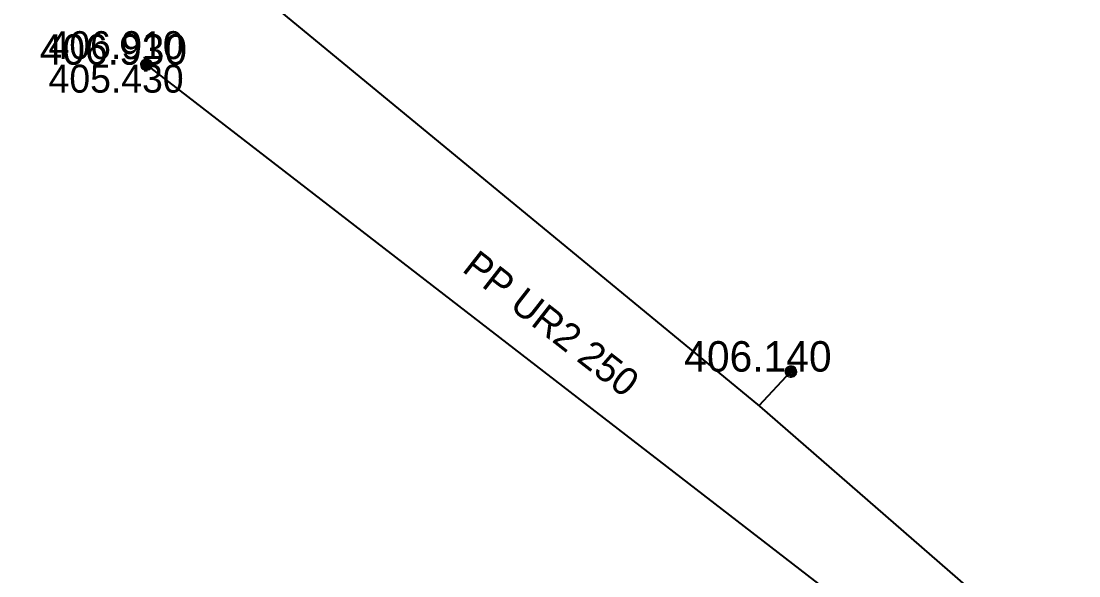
# Model space of a CAD drawing. Extents: x -873619 to -867639, y -1015082 to -1012326.
# Drawn here: x -868171.18 to -868129.55, y -1012747.99 to -1012726.16 of the extents above; entities that cross this region are included whole.
import ezdxf

# ---------------------------------------------------------------- set-up
doc = ezdxf.new("R2010")
doc.units = 0
doc.header["$LTSCALE"] = 0.44
for name, color, linetype, lineweight in [('1', 7, 'Continuous', 13), ('21', 7, 'Continuous', 35), ('32', 7, 'Continuous', 13), ('8', 7, 'Continuous', 13)]:
    doc.layers.add(name, color=color, linetype=linetype, lineweight=lineweight)

msp = doc.modelspace()

# ---------------------------------------------------------------- linework, layer by layer
at = {"layer": '1', "lineweight": 35}
msp.add_line((-868142.136, -1012741.287), (-868140.88, -1012739.954), dxfattribs=at)
msp.add_lwpolyline([(-868094.808, -1012782.506), (-868128.65, -1012753.034), (-868142.107, -1012741.315), (-868163.447, -1012723.713), (-868165.629, -1012721.604), (-868186.647, -1012703.368), (-868189.69, -1012700.802), (-868224.291, -1012669.746), (-868245.779, -1012651.034), (-868246.236, -1012651.387)], dxfattribs=at)
at = {"layer": '1'}
for points in [[(-868166.017, -1012727.87), (-868166.023, -1012727.818), (-868166.04, -1012727.768), (-868166.069, -1012727.724), (-868166.106, -1012727.687), (-868166.151, -1012727.66), (-868166.201, -1012727.643), (-868166.254, -1012727.639), (-868166.306, -1012727.646), (-868166.355, -1012727.665), (-868166.398, -1012727.694), (-868166.434, -1012727.733), (-868166.46, -1012727.778), (-868166.476, -1012727.829), (-868166.479, -1012727.881), (-868166.471, -1012727.933), (-868166.451, -1012727.982), (-868166.42, -1012728.025), (-868166.381, -1012728.059), (-868166.335, -1012728.085), (-868166.284, -1012728.099), (-868166.231, -1012728.101), (-868166.18, -1012728.091), (-868166.132, -1012728.07), (-868166.089, -1012728.039), (-868166.055, -1012727.998), (-868166.031, -1012727.952), (-868166.019, -1012727.901)], [(-868166.047, -1012727.87), (-868166.053, -1012727.821), (-868166.07, -1012727.775), (-868166.098, -1012727.735), (-868166.135, -1012727.703), (-868166.179, -1012727.681), (-868166.227, -1012727.67), (-868166.276, -1012727.67), (-868166.323, -1012727.683), (-868166.366, -1012727.707), (-868166.402, -1012727.74), (-868166.429, -1012727.781), (-868166.445, -1012727.828), (-868166.449, -1012727.877), (-868166.442, -1012727.925), (-868166.423, -1012727.97), (-868166.393, -1012728.01), (-868166.355, -1012728.041), (-868166.311, -1012728.061), (-868166.263, -1012728.071), (-868166.214, -1012728.069), (-868166.167, -1012728.054), (-868166.124, -1012728.029), (-868166.09, -1012727.995), (-868166.064, -1012727.953), (-868166.05, -1012727.906)], [(-868166.077, -1012727.87), (-868166.083, -1012727.825), (-868166.1, -1012727.783), (-868166.128, -1012727.748), (-868166.164, -1012727.721), (-868166.206, -1012727.704), (-868166.251, -1012727.699), (-868166.296, -1012727.705), (-868166.337, -1012727.724), (-868166.372, -1012727.752), (-868166.399, -1012727.789), (-868166.415, -1012727.831), (-868166.419, -1012727.876), (-868166.412, -1012727.921), (-868166.393, -1012727.962), (-868166.364, -1012727.996), (-868166.327, -1012728.022), (-868166.284, -1012728.038), (-868166.239, -1012728.041), (-868166.194, -1012728.033), (-868166.154, -1012728.013), (-868166.12, -1012727.984), (-868166.094, -1012727.946), (-868166.08, -1012727.903)], [(-868166.107, -1012727.87), (-868166.112, -1012727.829), (-868166.13, -1012727.792), (-868166.157, -1012727.761), (-868166.192, -1012727.74), (-868166.232, -1012727.729), (-868166.273, -1012727.731), (-868166.312, -1012727.744), (-868166.346, -1012727.768), (-868166.371, -1012727.8), (-868166.386, -1012727.838), (-868166.389, -1012727.879), (-868166.381, -1012727.919), (-868166.361, -1012727.955), (-868166.332, -1012727.984), (-868166.295, -1012728.003), (-868166.255, -1012728.011), (-868166.214, -1012728.007), (-868166.176, -1012727.992), (-868166.144, -1012727.966), (-868166.121, -1012727.932), (-868166.108, -1012727.893)], [(-868166.137, -1012727.87), (-868166.142, -1012727.834), (-868166.16, -1012727.802), (-868166.186, -1012727.777), (-868166.22, -1012727.762), (-868166.256, -1012727.759), (-868166.291, -1012727.767), (-868166.322, -1012727.787), (-868166.345, -1012727.815), (-868166.358, -1012727.849), (-868166.358, -1012727.886), (-868166.347, -1012727.921), (-868166.326, -1012727.95), (-868166.296, -1012727.971), (-868166.261, -1012727.981), (-868166.224, -1012727.979), (-868166.19, -1012727.965), (-868166.163, -1012727.942), (-868166.144, -1012727.91), (-868166.137, -1012727.875)], [(-868166.167, -1012727.87), (-868166.172, -1012727.839), (-868166.189, -1012727.813), (-868166.215, -1012727.796), (-868166.245, -1012727.789), (-868166.276, -1012727.793), (-868166.303, -1012727.81), (-868166.321, -1012727.834), (-868166.329, -1012727.865), (-868166.325, -1012727.895), (-868166.31, -1012727.923), (-868166.286, -1012727.942), (-868166.256, -1012727.951), (-868166.225, -1012727.948), (-868166.197, -1012727.934), (-868166.177, -1012727.91), (-868166.167, -1012727.881)], [(-868166.197, -1012727.87), (-868166.202, -1012727.846), (-868166.219, -1012727.828), (-868166.242, -1012727.819), (-868166.266, -1012727.822), (-868166.287, -1012727.836), (-868166.298, -1012727.858), (-868166.298, -1012727.883), (-868166.286, -1012727.904), (-868166.266, -1012727.918), (-868166.241, -1012727.921), (-868166.218, -1012727.912), (-868166.202, -1012727.894)], [(-868166.227, -1012727.87), (-868166.232, -1012727.855), (-868166.247, -1012727.849), (-868166.262, -1012727.853), (-868166.269, -1012727.867), (-868166.265, -1012727.882), (-868166.252, -1012727.891), (-868166.237, -1012727.888), (-868166.227, -1012727.876)], [(-868140.649, -1012739.954), (-868140.655, -1012739.902), (-868140.672, -1012739.852), (-868140.701, -1012739.808), (-868140.738, -1012739.771), (-868140.783, -1012739.744), (-868140.833, -1012739.727), (-868140.886, -1012739.723), (-868140.938, -1012739.73), (-868140.987, -1012739.749), (-868141.03, -1012739.778), (-868141.066, -1012739.817), (-868141.092, -1012739.862), (-868141.108, -1012739.913), (-868141.111, -1012739.965), (-868141.103, -1012740.017), (-868141.083, -1012740.066), (-868141.052, -1012740.109), (-868141.013, -1012740.143), (-868140.967, -1012740.169), (-868140.916, -1012740.183), (-868140.863, -1012740.185), (-868140.812, -1012740.175), (-868140.764, -1012740.154), (-868140.721, -1012740.123), (-868140.687, -1012740.082), (-868140.663, -1012740.036), (-868140.651, -1012739.985)], [(-868140.679, -1012739.954), (-868140.685, -1012739.905), (-868140.702, -1012739.859), (-868140.73, -1012739.819), (-868140.767, -1012739.787), (-868140.811, -1012739.765), (-868140.859, -1012739.754), (-868140.908, -1012739.754), (-868140.955, -1012739.767), (-868140.998, -1012739.791), (-868141.034, -1012739.824), (-868141.061, -1012739.865), (-868141.077, -1012739.912), (-868141.081, -1012739.961), (-868141.074, -1012740.009), (-868141.055, -1012740.054), (-868141.025, -1012740.094), (-868140.987, -1012740.125), (-868140.943, -1012740.145), (-868140.895, -1012740.155), (-868140.846, -1012740.153), (-868140.799, -1012740.138), (-868140.756, -1012740.113), (-868140.722, -1012740.079), (-868140.696, -1012740.037), (-868140.682, -1012739.99)], [(-868140.709, -1012739.954), (-868140.715, -1012739.909), (-868140.732, -1012739.867), (-868140.76, -1012739.832), (-868140.796, -1012739.805), (-868140.838, -1012739.788), (-868140.883, -1012739.783), (-868140.928, -1012739.789), (-868140.969, -1012739.808), (-868141.004, -1012739.836), (-868141.031, -1012739.873), (-868141.047, -1012739.915), (-868141.051, -1012739.96), (-868141.044, -1012740.005), (-868141.025, -1012740.046), (-868140.996, -1012740.08), (-868140.959, -1012740.106), (-868140.916, -1012740.122), (-868140.871, -1012740.125), (-868140.826, -1012740.117), (-868140.786, -1012740.097), (-868140.752, -1012740.068), (-868140.726, -1012740.03), (-868140.712, -1012739.987)], [(-868140.739, -1012739.954), (-868140.744, -1012739.913), (-868140.762, -1012739.876), (-868140.789, -1012739.845), (-868140.824, -1012739.824), (-868140.864, -1012739.813), (-868140.905, -1012739.815), (-868140.944, -1012739.828), (-868140.978, -1012739.852), (-868141.003, -1012739.884), (-868141.018, -1012739.922), (-868141.021, -1012739.963), (-868141.013, -1012740.003), (-868140.993, -1012740.039), (-868140.964, -1012740.068), (-868140.927, -1012740.087), (-868140.887, -1012740.095), (-868140.846, -1012740.091), (-868140.808, -1012740.076), (-868140.776, -1012740.05), (-868140.753, -1012740.016), (-868140.74, -1012739.977)], [(-868140.769, -1012739.954), (-868140.774, -1012739.918), (-868140.792, -1012739.886), (-868140.818, -1012739.861), (-868140.852, -1012739.846), (-868140.888, -1012739.843), (-868140.923, -1012739.851), (-868140.954, -1012739.871), (-868140.977, -1012739.899), (-868140.99, -1012739.933), (-868140.99, -1012739.97), (-868140.979, -1012740.005), (-868140.958, -1012740.034), (-868140.928, -1012740.055), (-868140.893, -1012740.065), (-868140.856, -1012740.063), (-868140.822, -1012740.049), (-868140.795, -1012740.026), (-868140.776, -1012739.994), (-868140.769, -1012739.959)], [(-868140.799, -1012739.954), (-868140.804, -1012739.923), (-868140.821, -1012739.897), (-868140.847, -1012739.88), (-868140.877, -1012739.873), (-868140.908, -1012739.877), (-868140.935, -1012739.894), (-868140.953, -1012739.918), (-868140.961, -1012739.949), (-868140.957, -1012739.979), (-868140.942, -1012740.007), (-868140.918, -1012740.026), (-868140.888, -1012740.035), (-868140.857, -1012740.032), (-868140.829, -1012740.018), (-868140.809, -1012739.994), (-868140.799, -1012739.965)], [(-868140.829, -1012739.954), (-868140.834, -1012739.93), (-868140.851, -1012739.912), (-868140.874, -1012739.903), (-868140.898, -1012739.906), (-868140.919, -1012739.92), (-868140.93, -1012739.942), (-868140.93, -1012739.967), (-868140.918, -1012739.988), (-868140.898, -1012740.002), (-868140.873, -1012740.005), (-868140.85, -1012739.996), (-868140.834, -1012739.978)], [(-868140.859, -1012739.954), (-868140.864, -1012739.939), (-868140.879, -1012739.933), (-868140.894, -1012739.937), (-868140.901, -1012739.951), (-868140.897, -1012739.966), (-868140.884, -1012739.975), (-868140.869, -1012739.972), (-868140.859, -1012739.96)]]:
    msp.add_lwpolyline(points, close=True, dxfattribs=at)
at = {"layer": '21'}
msp.add_line((-868166.248, -1012727.87), (-868134.19, -1012752.63), dxfattribs=at)
at = {"layer": '32'}
for points in [[(-868166.017, -1012727.87), (-868166.024, -1012727.818), (-868166.041, -1012727.768), (-868166.07, -1012727.724), (-868166.107, -1012727.687), (-868166.152, -1012727.66), (-868166.201, -1012727.643), (-868166.255, -1012727.639), (-868166.306, -1012727.646), (-868166.355, -1012727.665), (-868166.399, -1012727.694), (-868166.434, -1012727.733), (-868166.461, -1012727.778), (-868166.477, -1012727.829), (-868166.48, -1012727.881), (-868166.472, -1012727.933), (-868166.451, -1012727.982), (-868166.421, -1012728.025), (-868166.382, -1012728.059), (-868166.336, -1012728.085), (-868166.284, -1012728.099), (-868166.232, -1012728.101), (-868166.181, -1012728.091), (-868166.132, -1012728.07), (-868166.09, -1012728.039), (-868166.056, -1012727.998), (-868166.032, -1012727.952), (-868166.019, -1012727.901)], [(-868166.048, -1012727.87), (-868166.054, -1012727.821), (-868166.071, -1012727.775), (-868166.098, -1012727.735), (-868166.136, -1012727.703), (-868166.179, -1012727.681), (-868166.228, -1012727.67), (-868166.277, -1012727.67), (-868166.323, -1012727.683), (-868166.367, -1012727.707), (-868166.402, -1012727.74), (-868166.429, -1012727.781), (-868166.446, -1012727.828), (-868166.45, -1012727.877), (-868166.443, -1012727.925), (-868166.424, -1012727.97), (-868166.394, -1012728.01), (-868166.355, -1012728.041), (-868166.311, -1012728.061), (-868166.264, -1012728.071), (-868166.215, -1012728.069), (-868166.168, -1012728.054), (-868166.125, -1012728.029), (-868166.09, -1012727.995), (-868166.065, -1012727.953), (-868166.051, -1012727.906)], [(-868166.078, -1012727.87), (-868166.083, -1012727.825), (-868166.1, -1012727.783), (-868166.129, -1012727.748), (-868166.164, -1012727.721), (-868166.206, -1012727.704), (-868166.252, -1012727.699), (-868166.296, -1012727.705), (-868166.338, -1012727.724), (-868166.372, -1012727.752), (-868166.399, -1012727.789), (-868166.416, -1012727.831), (-868166.419, -1012727.876), (-868166.413, -1012727.921), (-868166.394, -1012727.962), (-868166.365, -1012727.996), (-868166.328, -1012728.022), (-868166.284, -1012728.038), (-868166.24, -1012728.041), (-868166.195, -1012728.033), (-868166.154, -1012728.013), (-868166.12, -1012727.984), (-868166.095, -1012727.946), (-868166.081, -1012727.903)], [(-868166.108, -1012727.87), (-868166.112, -1012727.829), (-868166.13, -1012727.792), (-868166.157, -1012727.761), (-868166.193, -1012727.74), (-868166.233, -1012727.729), (-868166.274, -1012727.731), (-868166.313, -1012727.744), (-868166.347, -1012727.768), (-868166.372, -1012727.8), (-868166.387, -1012727.838), (-868166.389, -1012727.879), (-868166.382, -1012727.919), (-868166.362, -1012727.955), (-868166.333, -1012727.984), (-868166.296, -1012728.003), (-868166.255, -1012728.011), (-868166.215, -1012728.007), (-868166.176, -1012727.992), (-868166.144, -1012727.966), (-868166.122, -1012727.932), (-868166.108, -1012727.893)], [(-868166.137, -1012727.87), (-868166.142, -1012727.834), (-868166.161, -1012727.802), (-868166.186, -1012727.777), (-868166.22, -1012727.762), (-868166.257, -1012727.759), (-868166.291, -1012727.767), (-868166.323, -1012727.787), (-868166.345, -1012727.815), (-868166.358, -1012727.849), (-868166.358, -1012727.886), (-868166.348, -1012727.921), (-868166.326, -1012727.95), (-868166.296, -1012727.971), (-868166.262, -1012727.981), (-868166.225, -1012727.979), (-868166.191, -1012727.965), (-868166.164, -1012727.942), (-868166.144, -1012727.91), (-868166.137, -1012727.875)], [(-868166.168, -1012727.87), (-868166.173, -1012727.839), (-868166.19, -1012727.813), (-868166.215, -1012727.796), (-868166.245, -1012727.789), (-868166.277, -1012727.793), (-868166.304, -1012727.81), (-868166.321, -1012727.834), (-868166.33, -1012727.865), (-868166.326, -1012727.895), (-868166.311, -1012727.923), (-868166.286, -1012727.942), (-868166.257, -1012727.951), (-868166.225, -1012727.948), (-868166.198, -1012727.934), (-868166.178, -1012727.91), (-868166.168, -1012727.881)], [(-868166.198, -1012727.87), (-868166.203, -1012727.846), (-868166.22, -1012727.828), (-868166.242, -1012727.819), (-868166.267, -1012727.822), (-868166.288, -1012727.836), (-868166.299, -1012727.858), (-868166.299, -1012727.883), (-868166.286, -1012727.904), (-868166.267, -1012727.918), (-868166.242, -1012727.921), (-868166.218, -1012727.912), (-868166.203, -1012727.894)], [(-868166.228, -1012727.87), (-868166.233, -1012727.855), (-868166.247, -1012727.849), (-868166.262, -1012727.853), (-868166.269, -1012727.867), (-868166.266, -1012727.882), (-868166.252, -1012727.891), (-868166.237, -1012727.888), (-868166.228, -1012727.876)]]:
    msp.add_lwpolyline(points, close=True, dxfattribs=at)
at = {"layer": '8'}
for points in [[(-868140.649, -1012739.954), (-868140.655, -1012739.902), (-868140.672, -1012739.852), (-868140.701, -1012739.808), (-868140.738, -1012739.771), (-868140.783, -1012739.744), (-868140.833, -1012739.727), (-868140.886, -1012739.723), (-868140.938, -1012739.73), (-868140.987, -1012739.749), (-868141.03, -1012739.778), (-868141.066, -1012739.817), (-868141.092, -1012739.862), (-868141.108, -1012739.913), (-868141.111, -1012739.965), (-868141.103, -1012740.017), (-868141.083, -1012740.066), (-868141.052, -1012740.109), (-868141.013, -1012740.143), (-868140.967, -1012740.169), (-868140.916, -1012740.183), (-868140.863, -1012740.185), (-868140.812, -1012740.175), (-868140.764, -1012740.154), (-868140.721, -1012740.123), (-868140.687, -1012740.082), (-868140.663, -1012740.036), (-868140.651, -1012739.985)], [(-868140.679, -1012739.954), (-868140.685, -1012739.905), (-868140.702, -1012739.859), (-868140.73, -1012739.819), (-868140.767, -1012739.787), (-868140.811, -1012739.765), (-868140.859, -1012739.754), (-868140.908, -1012739.754), (-868140.955, -1012739.767), (-868140.998, -1012739.791), (-868141.034, -1012739.824), (-868141.061, -1012739.865), (-868141.077, -1012739.912), (-868141.081, -1012739.961), (-868141.074, -1012740.009), (-868141.055, -1012740.054), (-868141.025, -1012740.094), (-868140.987, -1012740.125), (-868140.943, -1012740.145), (-868140.895, -1012740.155), (-868140.846, -1012740.153), (-868140.799, -1012740.138), (-868140.756, -1012740.113), (-868140.722, -1012740.079), (-868140.696, -1012740.037), (-868140.682, -1012739.99)], [(-868140.709, -1012739.954), (-868140.715, -1012739.909), (-868140.732, -1012739.867), (-868140.76, -1012739.832), (-868140.796, -1012739.805), (-868140.838, -1012739.788), (-868140.883, -1012739.783), (-868140.928, -1012739.789), (-868140.969, -1012739.808), (-868141.004, -1012739.836), (-868141.031, -1012739.873), (-868141.047, -1012739.915), (-868141.051, -1012739.96), (-868141.044, -1012740.005), (-868141.025, -1012740.046), (-868140.996, -1012740.08), (-868140.959, -1012740.106), (-868140.916, -1012740.122), (-868140.871, -1012740.125), (-868140.826, -1012740.117), (-868140.786, -1012740.097), (-868140.752, -1012740.068), (-868140.726, -1012740.03), (-868140.712, -1012739.987)], [(-868140.739, -1012739.954), (-868140.744, -1012739.913), (-868140.762, -1012739.876), (-868140.789, -1012739.845), (-868140.824, -1012739.824), (-868140.864, -1012739.813), (-868140.905, -1012739.815), (-868140.944, -1012739.828), (-868140.978, -1012739.852), (-868141.003, -1012739.884), (-868141.018, -1012739.922), (-868141.021, -1012739.963), (-868141.013, -1012740.003), (-868140.993, -1012740.039), (-868140.964, -1012740.068), (-868140.927, -1012740.087), (-868140.887, -1012740.095), (-868140.846, -1012740.091), (-868140.808, -1012740.076), (-868140.776, -1012740.05), (-868140.753, -1012740.016), (-868140.74, -1012739.977)], [(-868140.769, -1012739.954), (-868140.774, -1012739.918), (-868140.792, -1012739.886), (-868140.818, -1012739.861), (-868140.852, -1012739.846), (-868140.888, -1012739.843), (-868140.923, -1012739.851), (-868140.954, -1012739.871), (-868140.977, -1012739.899), (-868140.99, -1012739.933), (-868140.99, -1012739.97), (-868140.979, -1012740.005), (-868140.958, -1012740.034), (-868140.928, -1012740.055), (-868140.893, -1012740.065), (-868140.856, -1012740.063), (-868140.822, -1012740.049), (-868140.795, -1012740.026), (-868140.776, -1012739.994), (-868140.769, -1012739.959)], [(-868140.799, -1012739.954), (-868140.804, -1012739.923), (-868140.821, -1012739.897), (-868140.847, -1012739.88), (-868140.877, -1012739.873), (-868140.908, -1012739.877), (-868140.935, -1012739.894), (-868140.953, -1012739.918), (-868140.961, -1012739.949), (-868140.957, -1012739.979), (-868140.942, -1012740.007), (-868140.918, -1012740.026), (-868140.888, -1012740.035), (-868140.857, -1012740.032), (-868140.829, -1012740.018), (-868140.809, -1012739.994), (-868140.799, -1012739.965)], [(-868140.829, -1012739.954), (-868140.834, -1012739.93), (-868140.851, -1012739.912), (-868140.874, -1012739.903), (-868140.898, -1012739.906), (-868140.919, -1012739.92), (-868140.93, -1012739.942), (-868140.93, -1012739.967), (-868140.918, -1012739.988), (-868140.898, -1012740.002), (-868140.873, -1012740.005), (-868140.85, -1012739.996), (-868140.834, -1012739.978)], [(-868140.859, -1012739.954), (-868140.864, -1012739.939), (-868140.879, -1012739.933), (-868140.894, -1012739.937), (-868140.901, -1012739.951), (-868140.897, -1012739.966), (-868140.884, -1012739.975), (-868140.869, -1012739.972), (-868140.859, -1012739.96)]]:
    msp.add_lwpolyline(points, close=True, dxfattribs=at)

# ---------------------------------------------------------------- texts
at = {"layer": '1'}
for s, height, p in [('406.930 ', 1.2, (-868170.448, -1012727.87)), ('406.910 ', 1.1, (-868170.099, -1012727.65)), ('405.430 ', 1.1, (-868170.099, -1012728.97)), ('406.140 ', 1.2, (-868145.08, -1012739.954))]:
    msp.add_text(s, height=height, dxfattribs=at).set_placement(p)
msp.add_text('PP UR2 250', height=1.1, rotation=322, dxfattribs=at).set_placement((-868153.869, -1012735.977))

doc.saveas('drawing.dxf')
